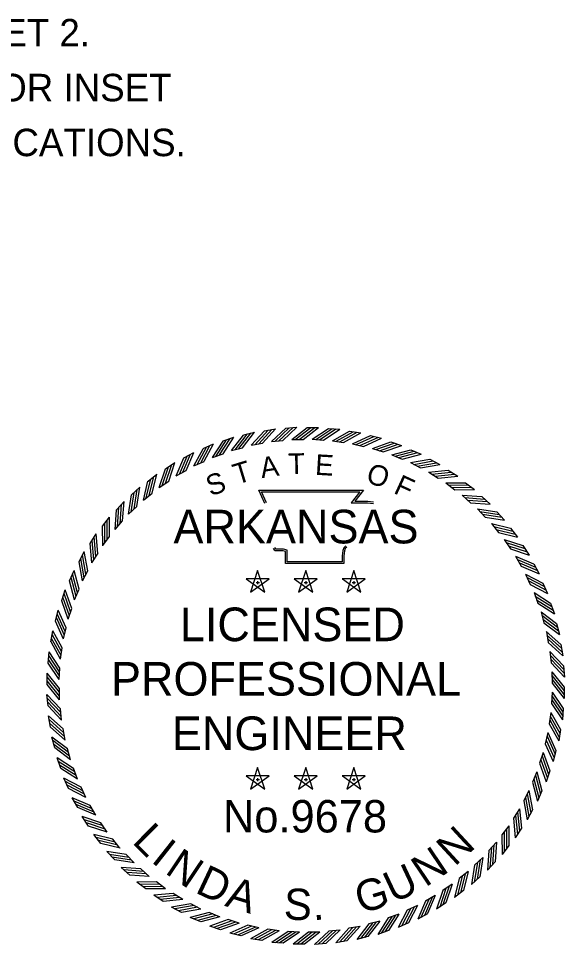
# Model space of a CAD drawing. Extents: x -24122 to 24238, y -8840 to 11381.
# Drawn here: x 13092 to 15717, y -8799 to -4346 of the extents above; entities that cross this region are included whole.
import ezdxf

# ---------------------------------------------------------------- set-up
doc = ezdxf.new("R2010")
doc.units = 0
doc.layers.add('R_Grid', color=7, linetype='Continuous')
doc.layers.add('STAMP', color=7, linetype='Continuous')

msp = doc.modelspace()

# ---------------------------------------------------------------- linework, layer by layer
at = {"layer": 'STAMP'}
for p, q in [((14274.6, -6328.5), (14328.3, -6319)), ((14376.6, -6316.3), (14430.9, -6311.3)), ((14479.8, -6313.2), (14534.3, -6313.2)), ((14581.9, -6317.3), (14636.2, -6321.3)), ((14075.4, -6377.8), (14126.8, -6359.7)), ((14174, -6349), (14226.7, -6335.2)), ((14683.7, -6330.6), (14737.5, -6339)), ((14784.1, -6352.1), (14837.1, -6365)), ((13979.6, -6414.7), (14029.2, -6392.3)), ((14116.8, -6424), (14169.7, -6410.1)), ((14211.5, -6398.5), (14265.3, -6389)), ((14307.9, -6380.8), (14362.3, -6375.8)), ((14405.4, -6371.2), (14460.1, -6371.2)), ((14503.4, -6369.7), (14557.9, -6373.7)), ((14601.2, -6376.3), (14655.2, -6384.8)), ((14698.2, -6390.9), (14751.2, -6403.8)), ((14882.4, -6382), (14934.1, -6399.2)), ((13887.1, -6459.3), (13934.7, -6432.9)), ((14024.7, -6457.3), (14076.1, -6439.1)), ((14793.5, -6413.5), (14845.4, -6430.7)), ((14886.7, -6443.8), (14936.9, -6465.3)), ((14977.9, -6419.8), (15028, -6441.2)), ((13798.6, -6511.4), (13843.9, -6481.2)), ((13935.5, -6498.1), (13985.3, -6475.7)), ((14977.1, -6481.8), (15025.4, -6507.4)), ((15069.9, -6465.4), (15118.1, -6490.8)), ((13714.7, -6570.7), (13757.3, -6536.8)), ((13850.1, -6546), (13897.8, -6519.6)), ((15064, -6527.1), (15110, -6556.6)), ((15157.9, -6518.4), (15203.8, -6547.8)), ((13768.8, -6600.9), (13814.3, -6570.6)), ((15146.9, -6579.4), (15190.3, -6612.6)), ((15241.2, -6578.5), (15284.5, -6611.6)), ((13636, -6636.7), (13675.7, -6599.4)), ((13692.4, -6662.3), (13735.2, -6628.4)), ((13563, -6708.9), (13599.5, -6668.5)), ((15225.2, -6638.4), (15265.7, -6675)), ((15319.2, -6645.3), (15359.6, -6681.8)), ((13621.4, -6729.8), (13661.2, -6692.5)), ((15298.3, -6703.7), (15335.7, -6743.5)), ((15391.5, -6718.3), (15428.7, -6758)), ((13496.2, -6787), (13529.2, -6743.7)), ((13556.1, -6803), (13592.7, -6762.4)), ((15365.8, -6774.7), (15399.7, -6817.5)), ((15457.4, -6797), (15491.3, -6839.7)), ((13436.1, -6870.2), (13465.5, -6824.4)), ((13497.1, -6881.2), (13530.3, -6837.8)), ((15427.2, -6851.1), (15457.5, -6896.6)), ((15516.7, -6880.9), (15546.9, -6926.2)), ((13383, -6958.2), (13408.5, -6910)), ((13444.8, -6964.1), (13474.3, -6918.1)), ((15482.1, -6932.4), (15508.5, -6980.1)), ((15568.8, -6969.4), (15595.2, -7017)), ((13337.5, -7050.2), (13358.9, -7000.1)), ((13399.5, -7051), (13425.1, -7002.8)), ((14241.7, -7000.7), (14207.6, -7105.3)), ((14275.7, -7105.2), (14241.8, -7000.6)), ((14472.8, -7000.7), (14438.7, -7105.3)), ((14506.8, -7105.2), (14472.9, -7000.6)), ((14703.9, -7000.7), (14669.8, -7105.3)), ((14737.9, -7105.2), (14704, -7000.6)), ((15530.1, -7017.8), (15552.5, -7067.6)), ((14296.6, -7040.6), (14186.7, -7040.5)), ((14186.7, -7040.6), (14275.7, -7105.4)), ((14207.7, -7105.2), (14296.8, -7040.7)), ((14233.9, -7058.2), (14250.2, -7058.2)), ((14241.8, -7052.3), (14241.8, -7066.1)), ((14527.8, -7040.6), (14417.8, -7040.5)), ((14417.9, -7040.6), (14506.8, -7105.4)), ((14438.8, -7105.2), (14527.9, -7040.7)), ((14465, -7058.2), (14481.3, -7058.2)), ((14472.9, -7052.3), (14472.9, -7066.1)), ((14758.9, -7040.6), (14648.9, -7040.5)), ((14649, -7040.6), (14737.9, -7105.4)), ((14670, -7105.2), (14759, -7040.7)), ((14696.1, -7058.2), (14712.4, -7058.2)), ((14704, -7052.3), (14704, -7066.1)), ((15613.5, -7061.9), (15635.8, -7111.5)), ((13299.6, -7145.7), (13316.9, -7094)), ((13361.5, -7141.4), (13383, -7091.2)), ((15570.9, -7107), (15589.1, -7158.4)), ((15650.3, -7157.7), (15668.5, -7209.1)), ((13269.8, -7244), (13282.7, -7191.1)), ((13331.2, -7234.6), (13348.4, -7182.8)), ((15604.1, -7199.2), (15618, -7252)), ((15679.1, -7256.3), (15693, -7309)), ((13248.2, -7344.4), (13256.7, -7290.6)), ((13308.6, -7330), (13321.5, -7276.9)), ((15629.7, -7293.8), (15639.1, -7347.6)), ((13235, -7446.3), (13239, -7391.9)), ((13294, -7426.9), (13302.5, -7372.9)), ((15647.3, -7390.2), (15652.3, -7444.6)), ((15699.7, -7356.9), (15709.1, -7410.6)), ((13287.4, -7524.7), (13291.4, -7470.2)), ((15711.9, -7458.9), (15716.9, -7513.2)), ((13230.3, -7548.9), (13229.8, -7494.4)), ((15656.9, -7487.7), (15657.4, -7542.4)), ((13288.9, -7622.7), (13288.4, -7568.1)), ((15715.6, -7561.6), (15716.1, -7616)), ((13234, -7651.5), (13229, -7597.3)), ((15658.4, -7585.7), (15654.4, -7640.2)), ((13246.2, -7753.5), (13236.7, -7699.8)), ((13298.5, -7720.2), (13293.5, -7665.9)), ((15651.9, -7683.5), (15643.4, -7737.5)), ((15710.8, -7664.2), (15706.8, -7718.5)), ((13316.2, -7816.7), (13306.7, -7762.9)), ((15637.2, -7780.5), (15624.3, -7833.5)), ((15697.6, -7766), (15689.1, -7819.8)), ((13266.7, -7854.1), (13252.9, -7801.4)), ((13341.7, -7911.3), (13327.8, -7858.5)), ((15614.7, -7875.8), (15597.4, -7927.7)), ((15676, -7866.4), (15663.1, -7919.4)), ((13295.5, -7952.7), (13277.4, -7901.3)), ((13375, -8003.5), (13356.8, -7952)), ((14241.7, -7948.3), (14207.6, -8052.9)), ((14275.7, -8052.8), (14241.8, -7948.2)), ((14472.8, -7948.3), (14438.7, -8052.9)), ((14506.8, -8052.8), (14472.9, -7948.2)), ((14703.9, -7948.3), (14669.8, -8052.9)), ((14737.9, -8052.8), (14704, -7948.2)), ((15584.3, -7969), (15562.8, -8019.2)), ((15646.2, -7964.7), (15629, -8016.4)), ((13332.4, -8048.6), (13310, -7998.9)), ((14296.6, -7988.2), (14186.7, -7988.1)), ((14186.7, -7988.2), (14275.7, -8053)), ((14207.7, -8052.8), (14296.8, -7988.3)), ((14233.9, -8005.8), (14250.2, -8005.8)), ((14241.8, -7999.9), (14241.8, -8013.7)), ((14527.8, -7988.2), (14417.8, -7988.1)), ((14417.9, -7988.2), (14506.8, -8053)), ((14438.8, -8052.8), (14527.9, -7988.3)), ((14465, -8005.8), (14481.3, -8005.8)), ((14472.9, -7999.9), (14472.9, -8013.7)), ((14758.9, -7988.2), (14648.9, -7988.1)), ((14649, -7988.2), (14737.9, -8053)), ((14670, -8052.8), (14759, -7988.3)), ((14696.1, -8005.8), (14712.4, -8005.8)), ((14704, -7999.9), (14704, -8013.7)), ((13415.7, -8092.6), (13393.3, -8042.8)), ((15546.3, -8059.4), (15520.8, -8107.7)), ((13377, -8141.1), (13350.6, -8093.4)), ((15608.4, -8060.2), (15586.9, -8110.3)), ((13463.7, -8178.1), (13437.3, -8130.3)), ((15501, -8146.3), (15471.6, -8192.3)), ((13429.1, -8229.6), (13398.9, -8184.2)), ((15562.8, -8152.2), (15537.3, -8200.4)), ((13518.6, -8259.3), (13488.3, -8213.9)), ((15448.7, -8229.2), (15415.6, -8272.6)), ((13488.4, -8313.5), (13454.5, -8270.8)), ((15509.8, -8240.2), (15480.4, -8286.1)), ((13580, -8335.7), (13546.1, -8292.9)), ((15389.7, -8307.5), (15353.1, -8348)), ((15449.7, -8323.5), (15416.6, -8366.8)), ((13554.4, -8392.2), (13517.1, -8352.4)), ((13647.5, -8406.8), (13610.2, -8366.9)), ((15324.5, -8380.6), (15284.6, -8418)), ((15382.9, -8401.5), (15346.3, -8441.9)), ((13626.6, -8465.2), (13586.2, -8428.6)), ((13720.7, -8472), (13680.1, -8435.4)), ((15253.4, -8448.1), (15210.6, -8482.1)), ((13704.7, -8532), (13661.4, -8498.9)), ((13798.9, -8531), (13755.5, -8497.9)), ((15309.9, -8473.8), (15270.1, -8511)), ((15177, -8509.5), (15131.5, -8539.8)), ((15231.2, -8539.7), (15188.5, -8573.6)), ((13787.9, -8592.1), (13742.1, -8562.7)), ((13881.8, -8583.3), (13835.8, -8553.9)), ((15095.8, -8564.4), (15048, -8590.8)), ((13875.9, -8645.1), (13827.7, -8619.6)), ((13968.7, -8628.6), (13920.5, -8603.1)), ((15010.3, -8612.4), (14960.5, -8634.8)), ((15147.3, -8599), (15101.9, -8629.2)), ((13967.9, -8690.7), (13917.8, -8669.2)), ((14059.1, -8666.6), (14008.9, -8645.1)), ((14152.3, -8697), (14100.5, -8679.7)), ((14921.2, -8653.2), (14869.7, -8671.4)), ((15058.8, -8651.1), (15011.1, -8677.5)), ((14063.4, -8728.5), (14011.7, -8711.3)), ((14247.7, -8719.6), (14194.6, -8706.6)), ((14344.6, -8734.2), (14290.6, -8725.7)), ((14734.3, -8712), (14680.6, -8721.4)), ((14829, -8686.4), (14776.2, -8700.3)), ((14966.3, -8695.8), (14916.6, -8718.1)), ((14161.7, -8758.3), (14108.8, -8745.4)), ((14262.1, -8779.9), (14208.3, -8771.4)), ((14442.4, -8740.7), (14387.9, -8736.7)), ((14540.4, -8739.2), (14485.8, -8739.7)), ((14637.9, -8729.6), (14583.6, -8734.6)), ((14771.8, -8761.4), (14719.1, -8775.3)), ((14870.4, -8732.6), (14819, -8750.8)), ((14364, -8793.1), (14309.6, -8789.1)), ((14466.6, -8797.9), (14412.1, -8798.4)), ((14569.2, -8794.2), (14515, -8799.2)), ((14671.2, -8782), (14617.5, -8791.4))]:
    msp.add_line(p, q, dxfattribs=at)
for points in [[(14247.3, -6392), (14310.4, -6321.9)], [(14265.2, -6389), (14328.3, -6319)], [(14307.8, -6380.9), (14376.5, -6316.3)], [(14325.3, -6379.4), (14394, -6314.9)], [(14344.1, -6377.3), (14412.8, -6312.7)], [(14362.2, -6375.8), (14430.9, -6311.2)], [(14405.4, -6371.3), (14479.7, -6313.3)], [(14422.9, -6371.4), (14497.3, -6313.5)], [(14441.8, -6371), (14516.2, -6313)], [(14460, -6371.2), (14534.3, -6313.2)], [(14503.4, -6369.7), (14581.8, -6317.4)], [(14520.9, -6371.2), (14599.2, -6318.8)], [(14539.8, -6372.2), (14618.2, -6319.8)], [(14557.8, -6373.7), (14636.2, -6321.3)], [(14058.9, -6445), (14109.7, -6365.5)], [(14076.1, -6439.1), (14126.8, -6359.6)], [(14116.8, -6424.1), (14173.9, -6349.1)], [(14133.8, -6419.8), (14190.9, -6344.8)], [(14152, -6414.6), (14209.1, -6339.6)], [(14169.6, -6410.1), (14226.7, -6335.1)], [(14211.4, -6398.5), (14274.6, -6328.5)], [(14228.7, -6395.7), (14291.9, -6325.6)], [(14601.2, -6376.3), (14683.6, -6330.6)], [(14618.5, -6379.2), (14700.9, -6333.5)], [(14637.2, -6381.7), (14719.7, -6336)], [(14655.1, -6384.7), (14737.6, -6339)], [(14698.1, -6390.9), (14784, -6352.2)], [(14715.1, -6395.2), (14801, -6356.5)], [(14733.6, -6399.3), (14819.5, -6360.5)], [(14751.2, -6403.8), (14837.1, -6365)], [(13951.5, -6491.1), (13995.6, -6407.7)], [(13968.6, -6482.9), (14012.7, -6399.6)], [(13985.3, -6475.6), (14029.3, -6392.3)], [(14024.6, -6457.4), (14075.4, -6377.9)], [(14041.2, -6451.7), (14092, -6372.2)], [(14793.5, -6413.5), (14882.3, -6382)], [(14810, -6419.2), (14898.9, -6387.7)], [(14828.1, -6424.8), (14917, -6393.3)], [(14845.3, -6430.7), (14934.2, -6399.1)], [(13865.4, -6537.8), (13902.4, -6451.1)], [(13881.8, -6528.2), (13918.8, -6441.5)], [(13897.8, -6519.6), (13934.8, -6432.9)], [(13935.5, -6498.1), (13979.5, -6414.8)], [(14886.6, -6443.9), (14977.8, -6419.8)], [(14902.7, -6450.9), (14993.9, -6426.8)], [(14920.3, -6458), (15011.4, -6433.9)], [(14936.9, -6465.3), (15028, -6441.2)], [(13799, -6580.6), (13828.7, -6491.1)], [(13814.2, -6570.6), (13843.9, -6481.2)], [(13850, -6546.1), (13887, -6459.4)], [(14977, -6481.8), (15069.8, -6465.4)], [(14992.4, -6490.2), (15085.3, -6473.7)], [(15009.4, -6498.7), (15102.2, -6482.2)], [(15025.3, -6507.3), (15118.1, -6490.8)], [(13735.2, -6628.4), (13757.4, -6536.8)], [(13768.8, -6601), (13798.5, -6511.5)], [(13783.5, -6591.4), (13813.2, -6501.9)], [(15063.9, -6527.1), (15157.8, -6518.4)], [(15078.6, -6536.7), (15172.5, -6528)], [(15094.8, -6546.6), (15188.6, -6537.8)], [(13692.4, -6662.4), (13714.6, -6570.8)], [(13706.3, -6651.6), (13728.5, -6560)], [(13720.8, -6639.5), (13743, -6547.9)], [(15110, -6556.5), (15203.8, -6547.7)], [(15146.8, -6579.4), (15241.1, -6578.5)], [(15160.6, -6590.2), (15254.9, -6589.2)], [(13634.3, -6718), (13648.8, -6624.9)], [(13647.8, -6704.8), (13662.4, -6611.6)], [(13661.1, -6692.5), (13675.7, -6599.3)], [(14276.8, -6677.9), (14247.8, -6615), (14750.3, -6614.7), (14708.3, -6667.5), (14742.4, -6667), (14770.9, -6666.7), (14799.4, -6669.8)], [(14284, -6674.6), (14260.2, -6623), (14733.7, -6622.7), (14691.6, -6675.6), (14742.5, -6675), (14770.6, -6674.6), (14798.6, -6677.7)], [(15175.9, -6601.4), (15270.2, -6600.4)], [(15190.3, -6612.5), (15284.5, -6611.6)], [(13592.7, -6762.5), (13599.5, -6668.4)], [(13621.4, -6729.9), (13635.9, -6636.8)], [(15225.1, -6638.4), (15319.1, -6645.2)], [(15238, -6650.3), (15332, -6657.1)], [(15252.3, -6662.7), (15346.3, -6669.5)], [(15265.7, -6675), (15359.7, -6681.8)], [(13556.1, -6803), (13562.9, -6709)], [(13568, -6790.1), (13574.8, -6696.1)], [(13580.4, -6775.8), (13587.2, -6681.8)], [(15298.2, -6703.7), (15391.4, -6718.2)], [(15310.1, -6716.6), (15403.2, -6731.1)], [(13519.1, -6852.2), (13518.1, -6757.9)], [(13530.2, -6837.9), (13529.2, -6743.6)], [(15323.4, -6730.1), (15416.5, -6744.7)], [(15335.7, -6743.4), (15428.8, -6758)], [(13497.1, -6881.3), (13496.2, -6787.1)], [(13507.9, -6867.5), (13506.9, -6773.2)], [(15365.7, -6774.7), (15457.4, -6796.9)], [(15376.5, -6788.6), (15468.1, -6810.8)], [(15388.6, -6803.1), (15480.2, -6825.3)], [(13454.4, -6949.5), (13445.7, -6855.7)], [(13464.3, -6933.4), (13455.5, -6839.5)], [(13474.2, -6918.2), (13465.4, -6824.3)], [(15399.7, -6817.5), (15491.4, -6839.7)], [(15427.1, -6851.1), (15516.6, -6880.8)], [(13444.8, -6964.2), (13436.1, -6870.3)], [(14671.1, -6888.5), (14662.5, -6895.5), (14659.7, -6905.9), (14656.8, -6931.9), (14656.8, -6966.7), (14376.3, -6966.7), (14376.3, -6919.8), (14376.3, -6909.4), (14364.9, -6905.9), (14325, -6905.9), (14317.9, -6895.1)], [(14666, -6882.3), (14655.5, -6890.9), (14651.8, -6904.4), (14648.9, -6931.5), (14648.9, -6958.7), (14384.3, -6958.7), (14384.3, -6919.8), (14384.3, -6903.5), (14366.1, -6897.9), (14329.3, -6897.9), (14324.6, -6890.7)], [(15436.7, -6865.8), (15526.2, -6895.5)], [(15447.6, -6881.3), (15537, -6911)], [(15457.5, -6896.5), (15547, -6926.2)], [(13407.9, -7035.7), (13391.4, -6942.9)], [(13416.4, -7018.8), (13399.9, -6925.9)], [(13425, -7002.8), (13408.5, -6910)], [(15482, -6932.3), (15568.7, -6969.3)], [(13399.5, -7051.1), (13383.1, -6958.3)], [(15490.4, -6947.7), (15577.1, -6984.7)], [(15499.9, -6964.1), (15586.6, -7001.1)], [(15508.5, -6980.1), (15595.2, -7017.1)], [(13368.6, -7125.4), (13344.5, -7034.3)], [(13375.7, -7107.9), (13351.6, -7016.7)], [(13383, -7091.2), (13358.9, -7000.1)], [(15530, -7017.8), (15613.4, -7061.8)], [(15537.1, -7033.8), (15620.4, -7077.9)], [(13361.6, -7141.5), (13337.5, -7050.3)], [(15545.2, -7050.9), (15628.6, -7095)], [(15552.5, -7067.6), (15635.9, -7111.6)], [(13342.5, -7200), (13310.9, -7111.1)], [(13348.4, -7182.8), (13316.8, -7094)], [(15570.8, -7106.9), (15650.2, -7157.7)], [(15576.5, -7123.5), (15655.9, -7174.3)], [(13331.2, -7234.7), (13299.7, -7145.8)], [(13336.9, -7218.1), (13305.4, -7129.2)], [(15583.2, -7141.2), (15662.6, -7192)], [(15589.1, -7158.4), (15668.5, -7209.1)], [(13317, -7294.6), (13278.2, -7208.6)], [(13321.4, -7277), (13282.7, -7191)], [(15604.1, -7199.1), (15679, -7256.2)], [(13308.6, -7330.1), (13269.9, -7244.1)], [(13312.9, -7313.1), (13274.2, -7227.1)], [(15608.4, -7216.1), (15683.3, -7273.3)], [(15613.6, -7234.3), (15688.6, -7291.4)], [(15618, -7251.9), (15693, -7309)], [(13302.4, -7373), (13256.7, -7290.6)], [(15629.6, -7293.7), (15699.6, -7356.9)], [(13294, -7427), (13248.3, -7344.5)], [(13296.9, -7409.7), (13251.2, -7327.2)], [(13299.4, -7390.9), (13253.7, -7308.5)], [(15632.5, -7311), (15702.5, -7374.2)], [(15636.2, -7329.6), (15706.2, -7392.7)], [(15639.2, -7347.5), (15709.2, -7410.6)], [(13291.4, -7470.3), (13239, -7391.9)], [(15647.2, -7390.1), (15711.8, -7458.8)], [(13288.9, -7507.3), (13236.5, -7428.9)], [(13289.9, -7488.4), (13237.5, -7410)], [(15648.7, -7407.6), (15713.2, -7476.3)], [(15650.8, -7426.4), (15715.4, -7495.1)], [(13287.4, -7524.8), (13235.1, -7446.4)], [(15652.3, -7444.5), (15716.9, -7513.2)], [(13288.4, -7568.2), (13229.7, -7494.3)], [(13288.4, -7586.3), (13229.7, -7512.5)], [(15656.9, -7487.7), (15715.5, -7561.5)], [(15656.9, -7505.2), (15715.5, -7579)], [(15657.5, -7524.1), (15716.1, -7597.9)], [(13289, -7605.2), (13230.3, -7531.4)], [(13289, -7622.8), (13230.3, -7549)], [(15657.5, -7542.3), (15716.1, -7616.1)], [(13293.5, -7665.9), (13228.9, -7597.2)], [(15656.9, -7603.2), (15709.3, -7681.6)], [(15658.4, -7585.7), (15710.8, -7664.1)], [(13295, -7684), (13230.4, -7615.3)], [(13297.1, -7702.8), (13232.6, -7634.1)], [(13298.6, -7720.3), (13234, -7651.6)], [(15654.5, -7640.2), (15706.8, -7718.5)], [(15656, -7622.1), (15708.3, -7700.5)], [(13306.7, -7762.9), (13236.7, -7699.8)], [(15648.9, -7700.8), (15694.7, -7783.2)], [(15651.8, -7683.5), (15697.5, -7765.9)], [(13309.6, -7780.8), (13239.6, -7717.7)], [(13313.3, -7799.4), (13243.3, -7736.3)], [(15643.4, -7737.4), (15689.1, -7819.9)], [(15646.4, -7719.5), (15692.1, -7802)], [(13316.2, -7816.7), (13246.2, -7753.6)], [(15637.2, -7780.4), (15676, -7866.3)], [(13327.8, -7858.5), (13252.8, -7801.4)], [(13332.3, -7876.1), (13257.3, -7819)], [(13337.5, -7894.3), (13262.5, -7837.2)], [(15624.4, -7833.5), (15663.1, -7919.4)], [(15628.8, -7815.9), (15667.6, -7901.8)], [(15632.9, -7797.4), (15671.7, -7883.3)], [(13341.8, -7911.3), (13266.8, -7854.2)], [(15614.6, -7875.8), (15646.2, -7964.6)], [(13356.8, -7952.1), (13277.3, -7901.3)], [(13362.6, -7969.2), (13283.2, -7918.5)], [(15603.4, -7910.4), (15634.9, -7999.3)], [(15608.9, -7892.4), (15640.5, -7981.2)], [(13369.4, -7986.9), (13289.9, -7936.2)], [(13375, -8003.5), (13295.6, -7952.8)], [(15584.3, -7969), (15608.3, -8060.1)], [(15597.5, -7927.6), (15629, -8016.5)], [(13393.3, -8042.9), (13310, -7998.9)], [(13400.6, -8059.5), (13317.3, -8015.5)], [(15570.2, -8002.6), (15594.2, -8093.7)], [(15577.2, -7985), (15601.3, -8076.2)], [(13408.8, -8076.6), (13325.4, -8032.6)], [(13415.8, -8092.7), (13332.5, -8048.6)], [(15546.3, -8059.3), (15562.8, -8152.1)], [(15562.9, -8019.2), (15587, -8110.4)], [(13437.3, -8130.4), (13350.6, -8093.4)], [(15529.5, -8091.7), (15545.9, -8184.5)], [(15538, -8074.7), (15554.4, -8167.6)], [(13445.9, -8146.3), (13359.2, -8109.3)], [(13455.5, -8162.7), (13368.7, -8125.7)], [(13463.8, -8178.1), (13377.1, -8141.1)], [(15501, -8146.2), (15509.8, -8240.1)], [(15520.8, -8107.6), (15537.3, -8200.5)], [(13488.3, -8213.9), (13398.9, -8184.2)], [(15471.6, -8192.3), (15480.4, -8286.1)], [(15481.6, -8177.1), (15490.3, -8271)], [(15491.4, -8160.9), (15500.2, -8254.8)], [(13498.3, -8229.1), (13408.8, -8199.4)], [(13509.1, -8244.6), (13419.6, -8214.9)], [(13518.7, -8259.3), (13429.2, -8229.6)], [(15448.7, -8229.1), (15449.7, -8323.4)], [(13546.1, -8293), (13454.5, -8270.8)], [(15415.6, -8272.6), (15416.6, -8366.8)], [(15426.8, -8258.3), (15427.7, -8352.5)], [(15437.9, -8243), (15438.9, -8337.2)], [(13557.2, -8307.3), (13465.6, -8285.1)], [(13569.3, -8321.9), (13477.7, -8299.7)], [(13580.1, -8335.7), (13488.5, -8313.5)], [(15377.8, -8320.3), (15371, -8414.3)], [(15389.7, -8307.4), (15382.9, -8401.4)], [(13610.2, -8367), (13517, -8352.4)], [(13622.5, -8380.4), (13529.3, -8365.8)], [(15353.2, -8348), (15346.3, -8442)], [(15365.5, -8334.6), (15358.6, -8428.6)], [(13635.7, -8393.9), (13542.6, -8379.3)], [(13647.6, -8406.8), (13554.5, -8392.2)], [(15298, -8405.7), (15283.5, -8498.8)], [(15311.6, -8392.4), (15297, -8485.6)], [(15324.5, -8380.5), (15309.9, -8473.7)], [(13680.2, -8435.5), (13586.1, -8428.6)], [(13693.5, -8447.8), (13599.5, -8440.9)], [(13707.8, -8460.1), (13613.8, -8453.3)], [(15239.6, -8458.8), (15217.4, -8550.4)], [(15253.4, -8448), (15231.2, -8539.7)], [(15284.7, -8418), (15270.1, -8511.1)], [(13720.7, -8472), (13626.7, -8465.2)], [(13755.6, -8497.9), (13661.3, -8498.9)], [(15210.7, -8482), (15188.5, -8573.7)], [(15225, -8470.9), (15202.8, -8562.5)], [(13769.9, -8509.1), (13675.6, -8510)], [(13785.2, -8520.2), (13690.9, -8521.2)], [(13799, -8531), (13704.7, -8532)], [(15131.6, -8539.8), (15101.9, -8629.3)], [(15146.8, -8529.9), (15117.1, -8619.4)], [(15162.3, -8519), (15132.6, -8608.5)], [(15177, -8509.4), (15147.3, -8598.9)], [(13835.9, -8553.9), (13742, -8562.7)], [(13851.1, -8563.9), (13757.2, -8572.6)], [(13867.2, -8573.7), (13773.3, -8582.5)], [(13881.9, -8583.3), (13788, -8592.1)], [(15048.1, -8590.8), (15011.1, -8677.6)], [(15064, -8582.2), (15027, -8668.9)], [(15080.4, -8572.7), (15043.4, -8659.4)], [(15095.8, -8564.3), (15058.8, -8651)], [(13920.5, -8603.1), (13827.7, -8619.6)], [(13936.5, -8611.8), (13843.6, -8628.2)], [(13953.4, -8620.3), (13860.6, -8636.7)], [(13968.8, -8628.6), (13876, -8645.1)], [(14960.6, -8634.8), (14916.6, -8718.2)], [(14977.2, -8627.5), (14933.2, -8710.9)], [(14994.3, -8619.4), (14950.3, -8702.7)], [(15010.4, -8612.3), (14966.3, -8695.7)], [(14008.9, -8645.2), (13917.8, -8669.3)], [(14025.6, -8652.5), (13934.4, -8676.5)], [(14043.1, -8659.5), (13952, -8683.6)], [(14059.2, -8666.6), (13968, -8690.7)], [(14100.5, -8679.8), (14011.7, -8711.3)], [(14869.8, -8671.4), (14819, -8750.8)], [(14886.9, -8665.5), (14836.2, -8744.9)], [(14904.6, -8658.8), (14853.9, -8738.2)], [(14921.2, -8653.1), (14870.5, -8732.5)], [(14117.7, -8685.7), (14028.8, -8717.2)], [(14135.8, -8691.3), (14046.9, -8722.8)], [(14152.4, -8696.9), (14063.5, -8728.5)], [(14194.7, -8706.7), (14108.7, -8745.4)], [(14212.3, -8711.1), (14126.3, -8749.9)], [(14230.7, -8715.2), (14144.8, -8754)], [(14247.7, -8719.5), (14161.8, -8758.3)], [(14290.7, -8725.7), (14208.2, -8771.4)], [(14680.6, -8721.5), (14617.5, -8791.5)], [(14698.5, -8718.5), (14635.4, -8788.5)], [(14717.1, -8714.8), (14654, -8784.8)], [(14734.4, -8711.9), (14671.3, -8781.9)], [(14776.2, -8700.3), (14719.1, -8775.3)], [(14793.8, -8695.9), (14736.7, -8770.9)], [(14812, -8690.7), (14754.9, -8765.6)], [(14829, -8686.4), (14771.9, -8761.3)], [(14308.6, -8728.7), (14226.2, -8774.4)], [(14327.4, -8731.2), (14244.9, -8777)], [(14344.7, -8734.1), (14262.2, -8779.8)], [(14388, -8736.8), (14309.6, -8789.1)], [(14406.1, -8738.3), (14327.7, -8790.6)], [(14425, -8739.3), (14346.6, -8791.6)], [(14442.5, -8740.7), (14364.1, -8793.1)], [(14485.8, -8739.8), (14412, -8798.4)], [(14504, -8739.8), (14430.2, -8798.4)], [(14522.9, -8739.2), (14449.1, -8797.8)], [(14540.5, -8739.2), (14466.7, -8797.8)], [(14583.6, -8734.6), (14514.9, -8799.2)], [(14601.7, -8733.1), (14533, -8797.7)], [(14620.5, -8731), (14551.8, -8795.5)], [(14638, -8729.5), (14569.3, -8794.1)]]:
    msp.add_lwpolyline(points, dxfattribs=at)

# ---------------------------------------------------------------- texts
at = {"layer": 'R_Grid'}
for s, p in [('1.  BRIDGE DATA IS ON PLAN SHEET 2. ', (10120.4, -4480.1)), ('2.  REFER TO SPECIAL DETAILS FOR INSET', (10120.4, -4744.1)), ('    ENLARGEMENTS AT BRIDGE LOCATIONS.', (10120.4, -5008.1))]:
    msp.add_text(s, height=132, dxfattribs=at).set_placement(p)
at = {"layer": 'STAMP'}
for s, height, rotation, p in [('A', 99.1, 8.6788, (14261.5, -6556.9)), ('T', 99.1, 1.4789, (14389.5, -6537.2)), ('E', 99.1, 356.672, (14516.3, -6540.2)), ('T', 99.1, 16.9015, (14141.1, -6588.4)), ('O', 99.1, 341.2218, (14757, -6574.2)), ('S', 99.1, 19.7726, (14015.1, -6644.9)), ('F', 99.1, 335.3628, (14890.6, -6626.5)), ('L', 150.5, 315.1295, (13633.3, -8308.4)), ('N', 150.5, 42.6817, (15189.2, -8427.4)), ('I', 150.5, 321.696, (13724.8, -8399.5)), ('N', 150.5, 326.0736, (13791.4, -8454.2)), ('N', 150.5, 33.9264, (15048.3, -8526.2)), ('U', 150.5, 25.1712, (14893.9, -8602.4)), ('D', 150.5, 334.8288, (13936.1, -8547.5)), ('A', 150.5, 342.8544, (14079.8, -8612.8)), ('G', 150.5, 16.7808, (14736.7, -8652.6)), ('S', 150.5, 357.8112, (14365.9, -8678.6)), ('.', 150.5, 5.1072, (14509.3, -8683.2))]:
    msp.add_text(s, height=height, rotation=rotation, dxfattribs=at).set_placement(p)
for s, height, p in [('ARKANSAS', 161.78, (13837, -6870.4)), ('LICENSED', 161.78, (13867.8, -7340.6)), ('PROFESSIONAL', 161.779, (13536.5, -7602.6)), ('ENGINEER', 161.78, (13829.3, -7864.5)), ('No.9678', 156, (14075.1, -8260.5))]:
    msp.add_text(s, height=height, dxfattribs=at).set_placement(p)

doc.saveas('drawing.dxf')
